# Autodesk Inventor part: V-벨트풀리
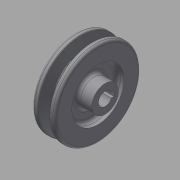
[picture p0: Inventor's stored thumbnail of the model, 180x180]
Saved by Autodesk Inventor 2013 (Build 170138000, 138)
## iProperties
Created: 2015-02
Part Number: V-벨트풀리
Material: 일반
Document SubType Name: Modeling
Designer: Administrator
Density: 1 g/cm^3
Author: Administrator
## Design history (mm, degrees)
sketch "스케치1"
  geometry: L1 (-12.5, 0)-(12.5, 0); L2 (-12.5, -5.5)-(12.5, -5.5); L3 (12.5, -5.5)-(12.5, -11); L4 (12.5, -11)-(0.5, -11); L5 (0.5, -11)-(0.5, -21.5); L6 (0.5, -21.5)-(6.5, -21.5); L7 (6.5, -21.5)-(6.5, -35.2); L8 (6.5, -35.2)-(1.825, -35.2); L9 (1.825, -35.2)-(-0.926, -26.2); L10 (-0.926, -26.2)-(-5.074, -26.2); L11 (-5.074, -26.2)-(-7.825, -35.2); L12 (-7.825, -35.2)-(-12.5, -35.2); L13 (-7, -32.5)-(1, -32.5); L14 (-12.5, -21.5)-(-6.5, -21.5); L15 (-6.5, -21.5)-(-6.5, -11); L16 (-6.5, -11)-(-12.5, -11); L17 (-12.5, -35.2)-(-12.5, -21.5); L18 (-12.5, -11)-(-12.5, -5.5); 11 further points
  constraints: 36 end point, 10 midpoint, 10 parallel, 4 perpendicular, 3 horizontal alignment, 3 vertical alignment, 2 coincident, 2 equal length, 2 point on line, 2 vertical, 1 horizontal
  dimensions: "d0" = 25 distance of L1.start L1.end; "d1" = 11 diameter of L2 L1; "d2" = 8 distance of L13.start L13.end; "d3" = 34 deg angle of L11 L9; "d4" = 65 diameter of L13 L1; "d5" = 2.7 distance between parallel lines of L13 L12; "d6" = 6.3 distance between parallel lines of L10 L13; "d9" = 6 distance between parallel lines of L7 L5; "d10" = 43 diameter of point (-9.5, -21.5) L1; "d11" = 22 diameter of L4 L1; "d12" = 19 distance between parallel lines of L7 L17; "d13" = 6 distance between parallel lines of L17 L15
revolve "회전1" sketch "스케치1" stored, may be unused: angle "d14" = 90 deg
sketch "스케치2"
  geometry: L1 (-2, 5.123)-(-2, 7.3); L2 (-2, 7.3)-(2, 7.3); L3 (2, 7.3)-(2, 5.123); C1 r 11 at (0, 0) reference; A1 r 5.5 centre (0, 0) between (-2, 5.123) and (2, 5.123) reference
  constraints: 6 end point, 2 parallel, 2 point on circle, 1 perpendicular, 1 vertical
  dimensions: "d15" = 7.3 distance from line of L2 C1.centre; "d16" = 4 distance between parallel lines of L3 L1
extrude "돌출1" cut sketch "스케치2" stored distance "d17" = 10; taper "d18" = 0 deg
fillet "모깎기1" dims "d19" = 0.5, "d20" = 2, "d21" = 3
node "솔리드1"
other parameters: "d7" = 19, "d8" = 6
